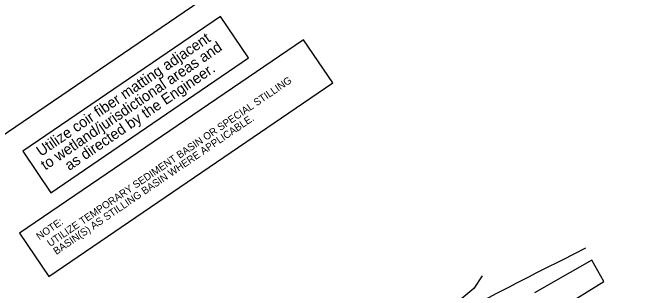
# Model space of a CAD drawing. Extents: x 2357856 to 2382083, y 331121 to 347536.
# Drawn here: x 2380554 to 2381167, y 332980 to 333255 of the extents above; entities that cross this region are included whole.
import ezdxf

# ---------------------------------------------------------------- set-up
doc = ezdxf.new("R2010")
doc.units = 0
for name, color, linetype in [('Default', 7, 'Continuous'), ('EC Title Sheet CELL', 7, 'Continuous'), ('PSRM Summary Sheet CELL', 7, 'Continuous'), ('Scratch_Level_7', 7, 'Continuous'), ('Sheet Data Field CELL', 7, 'Continuous'), ('Sheet_Named_Boundary', 7, 'Continuous'), ('Sheet_North_Arrow_CELL', 7, 'Continuous')]:
    doc.layers.add(name, color=color, linetype=linetype)

# ---------------------------------------------------------------- blocks, each defined once
blk = doc.blocks.new('SBNT')
at = {"layer": 'Scratch_Level_7'}
blk.add_lwpolyline([(0.09369, 0.01433), (-0.09477, 0.01433), (-0.09477, -0.01437), (0.09369, -0.01437)], close=True, dxfattribs=at)
for s, height, p in [('NOTE:  ', 0.004, (-0.08792, 0.005)), ('     UTILIZE TEMPORARY SEDIMENT BASIN OR SPECIAL STILLING', 0.0039998, (-0.09251, -0.00149)), ('     BASIN(S) AS STILLING BASIN WHERE APPLICABLE.', 0.004, (-0.09221, -0.007))]:
    blk.add_text(s, height=height, dxfattribs=at).set_placement(p)

msp = doc.modelspace()

# ---------------------------------------------------------------- linework, layer by layer
at = {"layer": 'Default'}
msp.add_lwpolyline([(2380245.38, 332929.65), (2381505.45, 333788.59), (2382082.78, 332941.65), (2381016.75, 332214.98)], close=True, dxfattribs=at)
at = {"layer": 'EC Title Sheet CELL'}
msp.add_lwpolyline([(2381017.68, 332994.48), (2381009.42, 332981.94), (2380976.31, 332954.46)], dxfattribs=at)
at = {"layer": 'PSRM Summary Sheet CELL'}
msp.add_lwpolyline([(2380564.1, 333117.5), (2380592, 333076.57), (2380787.15, 333209.62), (2380759.25, 333250.55)], close=True, dxfattribs=at)
at = {"layer": 'Sheet Data Field CELL'}
msp.add_lwpolyline([(2381095.37, 332962.59), (2381137.68, 332988.81), (2381126.06, 333009.81), (2381104.38, 332997.7), (2381069.47, 332977.56)], dxfattribs=at)
at = {"layer": 'Sheet_Named_Boundary'}
msp.add_line((2381119.53, 333021.89), (2381097.24, 333010.36), dxfattribs=at)
msp.add_arc((2382777.93, 329631.25), 3774.01, 116.44459, 118.25044, dxfattribs=at)

# ---------------------------------------------------------------- block references
at = {"layer": 'Sheet_North_Arrow_CELL', "xscale": 1800, "yscale": 1799.9999999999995, "rotation": 34.284899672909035}
msp.add_blockref('SBNT', (2380716.33, 333111.36), dxfattribs=at)

# ---------------------------------------------------------------- texts
at = {"layer": 'PSRM Summary Sheet CELL'}
for s, p in [('Utilize coir fiber matting adjacent', (2380582.14, 333111.93)), ('to wetland/jurisdictional areas and', (2380586.49, 333098.38)), ('as directed by the Engineer.', (2380610.15, 333098))]:
    msp.add_text(s, height=10.5415, rotation=34.2849, dxfattribs=at).set_placement(p)

doc.saveas('drawing.dxf')
